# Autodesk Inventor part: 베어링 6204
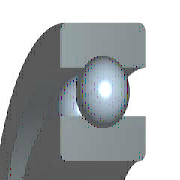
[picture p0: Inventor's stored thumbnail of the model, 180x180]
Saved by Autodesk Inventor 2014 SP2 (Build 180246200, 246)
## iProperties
IsCustomPart: 0
Created: 2015-12
Part Number: 베어링 6204
Material: 강철, 연강
Description: 깊은 그루브 볼 베어링
Document SubType Name: Modeling
Standard: KS B 2023
Designer: mdu
Standards Organization: KS
Language: ko-KR
Size Designation: 6204 - 20 x 47 x 14
Categories: <MemberInstance><Categories><Category DisplayName="샤프트 부품" InternalName="7f7aeb1f-a693-4053-b835-cee3144e0d98" Mnemonic="SHFT"><Category DisplayName="베어링" Inter
Density: 7.86 g/cm^3
Mass: 104.255 g
Surface Area: 87.8912 cm^2
Volume: 13.264 cm^3
Appearance: 강철
Author: mud
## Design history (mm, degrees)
sketch "스케치" dims "d0" = 7.02 (= -0.26 x WD + 0.26 x BD)
  geometry: L1 (3.49, 16.75)-(10.51, 16.75); L2 (7, 16.75)-(7, 13.24); L3 (7, 16.75)-(7, 20.26); L4 (4.392, 14.401)-(0, 14.401); L5 (0, 10)-(14, 10); L6 (4.392, 19.099)-(0, 19.099); L7 (0, 23.5)-(14, 23.5); L8 (14, 10)-(14, 14.401); L9 (9.608, 14.401)-(14, 14.401); L10 (9.608, 19.099)-(14, 19.099); L11 (14, 23.5)-(14, 19.099); L12 (-1.4, 0)-(8.4, 0) reference; L13 (0, -0.3)-(0, 5.3) reference
  constraints: 22 end point, 4 point on line, 2 collinear, 2 perpendicular, 2 symmetric about line, 1 midpoint, 1 parallel, 14 other
  dimensions: "d9" = 20 diameter of L5 L12 (= WD); "d11" = 47 diameter of L7 L12 (= BD); "d12" = 14 distance between parallel lines of L8 L13 (= KB); "d13" = 28.802 diameter of L9 L12 (= 0.326 x BD + 0.674 x WD)
revolve "본체" stored, may be unused: angle "d6" = 90 deg
revolve "볼" stored, may be unused: angle "d7" = 90 deg
pattern_circular "IDS_ARRAYBALL[SIMPL:T]" dims angle "d3" = 360 deg
body "Solid1"
fillet "모깎기1" dims "d1" = 1 (= KRS)
other parameters: "WD" = 20 [user parameter; used in 5 equation terms], "BD" = 47 [user parameter; used in 5 equation terms], "KB" = 14 [user parameter; used in 1 equation term], "KRS" = 1 [user parameter; used in 1 equation term], "d4" = 0, "d5" = 0, "d8" = 0, "d14" = 0, "d15" = 0, "BBA" = 0 [user parameter], "BC0" = 6550000 [user parameter], "BC" = 1.27e+07 [user parameter], "BR" = 23.5 (= 0.5 x BD) [user parameter]
